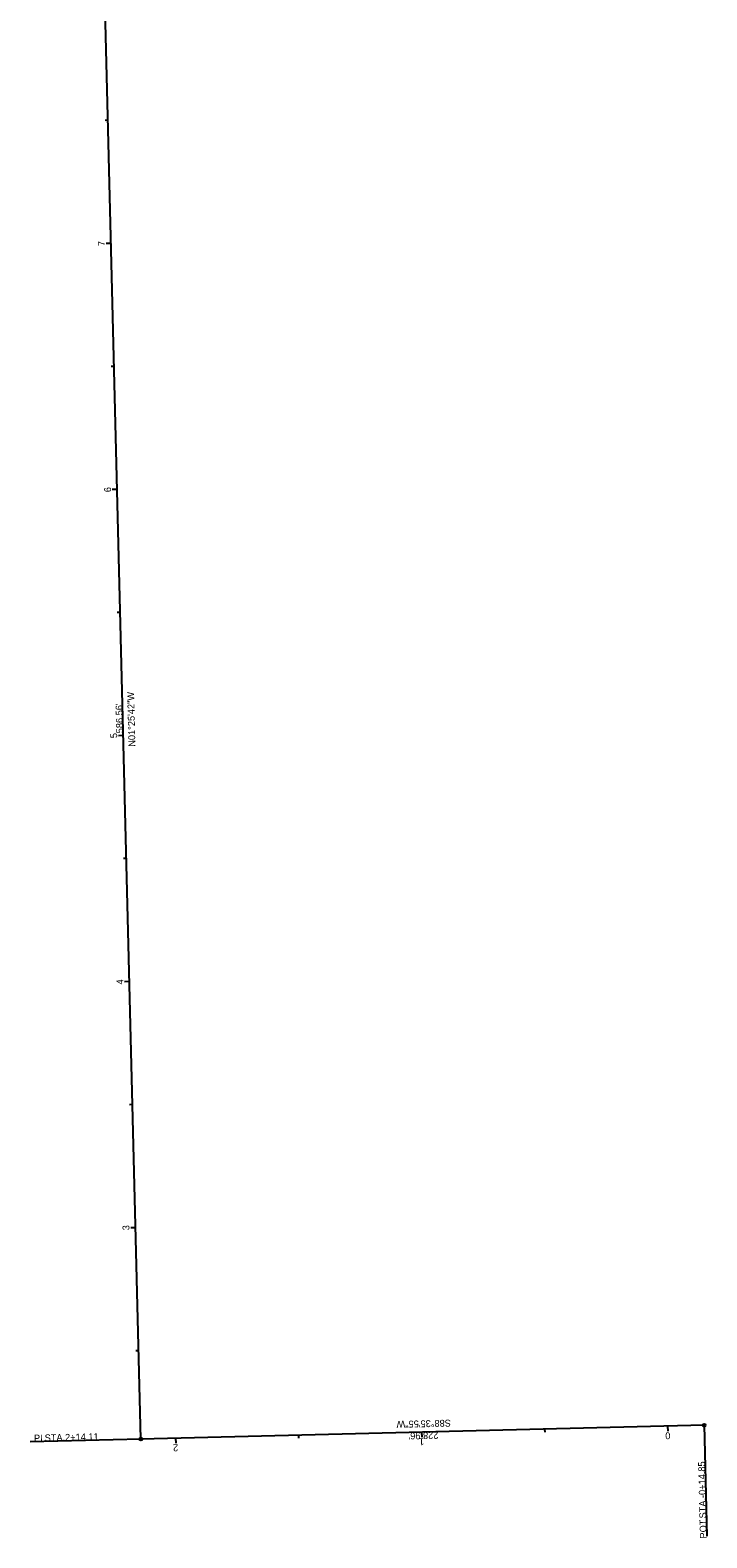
# Model space of a CAD drawing. Extents: x 140402 to 140969, y 345095 to 350073.
# Drawn here: x 140694 to 140969, y 345095 to 345707 of the extents above; entities that cross this region are included whole.
import ezdxf

# ---------------------------------------------------------------- set-up
doc = ezdxf.new("R2010")
doc.units = 0
for name, color, linetype in [('_CIVIL_CONSTRUCTION', 7, 'Continuous'), ('DR_X_Cells', 7, 'Continuous'), ('SC_Scratch1', 7, 'Continuous'), ('SN_X_Public', 7, 'Continuous'), ('SV_X_Control_Cells_Found', 7, 'Continuous'), ('SV_X_Mon_Cells_Found', 7, 'Continuous')]:
    doc.layers.add(name, color=color, linetype=linetype)

msp = doc.modelspace()

# ---------------------------------------------------------------- linework, layer by layer
at = {"layer": 'SC_Scratch1'}
for p, q in [((140968.27, 345140.7), (140969.37, 345095.72)), ((140739.38, 345135.1), (140694.39, 345133.98))]:
    msp.add_line(p, q, dxfattribs=at)
for centre in [(140968.27, 345140.7), (140739.38, 345135.1)]:
    msp.add_circle(centre, 0.6, dxfattribs=at)
at = {"layer": 'SN_X_Public'}
for p, q in [((140726.02, 345670.83), (140724.82, 345670.8)), ((140727.27, 345620.84), (140725.27, 345620.79)), ((140728.51, 345570.86), (140727.31, 345570.83)), ((140729.76, 345520.87), (140727.76, 345520.82)), ((140731.01, 345470.89), (140729.81, 345470.86)), ((140732.25, 345420.9), (140730.25, 345420.85)), ((140733.5, 345370.92), (140732.3, 345370.89)), ((140734.74, 345320.94), (140732.75, 345320.89)), ((140735.99, 345270.95), (140734.79, 345270.92)), ((140737.24, 345220.97), (140735.24, 345220.92)), ((140738.48, 345170.98), (140737.28, 345170.95)), ((140903.44, 345139.12), (140903.47, 345137.92)), ((140953.42, 345140.34), (140953.47, 345138.34)), ((140753.48, 345135.45), (140753.53, 345133.45)), ((140803.47, 345136.67), (140803.5, 345135.47)), ((140853.45, 345137.89), (140853.5, 345135.89))]:
    msp.add_line(p, q, dxfattribs=at)
at = {"layer": 'SV_X_Control_Cells_Found'}
msp.add_line((140739.38, 345135.1), (140720.96, 345873.69), dxfattribs=at)
at = {"layer": 'SV_X_Mon_Cells_Found'}
for p, q in [((140739.38, 345135.1), (140724.76, 345721.48)), ((140968.27, 345140.7), (140739.38, 345135.1))]:
    msp.add_line(p, q, dxfattribs=at)

# ---------------------------------------------------------------- texts
at = {"layer": '_CIVIL_CONSTRUCTION'}
for s, rotation, p in [('N01°25\'42"W', 91.42845, (140737.17, 345416.39)), ('S88°35\'55"W', 181.40131, (140865.33, 345142.99))]:
    msp.add_text(s, height=2.8, rotation=rotation, dxfattribs=at).set_placement(p)
at = {"layer": 'DR_X_Cells'}
for s, rotation, p in [("586.56'", 91.42845, (140732.19, 345421.86)), ("228.96'", 181.40131, (140860.26, 345138.02))]:
    msp.add_text(s, height=2.8, rotation=rotation, dxfattribs=at).set_placement(p)
at = {"layer": 'SC_Scratch1'}
for s, rotation, p in [('PI', 1.42845, (140695.98, 345134.06)), (' STA. ', 1.42845, (140699.29, 345134.14)), ('2+14.11', 1.42845, (140708.61, 345134.37)), ('-0+14.85', 91.40131, (140968.96, 345111.18)), (' STA. ', 91.40131, (140969.19, 345101.86)), ('POT', 91.40131, (140969.36, 345094.73))]:
    msp.add_text(s, height=2.8, rotation=rotation, dxfattribs=at).set_placement(p)
at = {"layer": 'SN_X_Public'}
for s, rotation, p in [('7', 91.42845, (140724.79, 345619.77)), ('6', 91.42845, (140727.29, 345519.79)), ('5', 91.42845, (140729.78, 345419.87)), ('4', 91.42845, (140732.27, 345319.83)), ('3', 91.42845, (140734.76, 345219.94)), ('2', 181.40131, (140754.52, 345132.97)), ('1', 181.40131, (140854.5, 345135.42)), ('0', 181.40131, (140954.52, 345137.87))]:
    msp.add_text(s, height=2.8, rotation=rotation, dxfattribs=at).set_placement(p)

doc.saveas('drawing.dxf')
